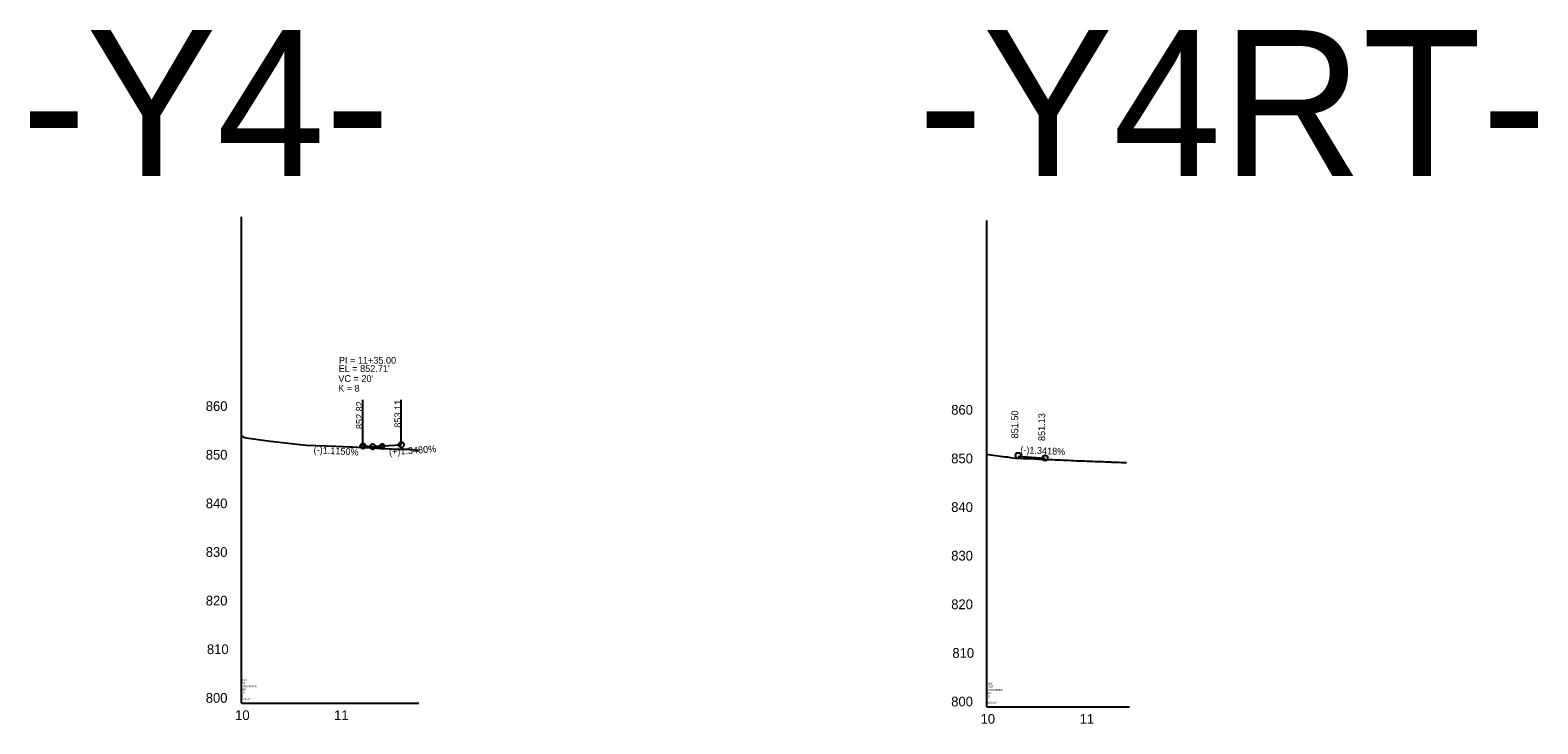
# Model space of a CAD drawing. Extents: x 570622 to 580296, y -55533 to -48575.
# Drawn here: x 577354 to 578904, y -55304 to -54591 of the extents above; entities that cross this region are included whole.
import ezdxf

# ---------------------------------------------------------------- set-up
doc = ezdxf.new("R2010")
doc.units = 0
for name, color, linetype in [('Default', 7, 'Continuous'), ('Exist Profile Cell', 7, 'Continuous'), ('Exist Vertical Profile Ground Line', 7, 'Continuous'), ('Exist Vertical Profile Horizontal Axis Label Major', 7, 'Continuous'), ('Exist Vertical Profile Vertical Axis Label', 7, 'Continuous'), ('Prop Vertical Profile Curve Label', 7, 'Continuous'), ('Prop Vertical Profile Grade', 7, 'Continuous'), ('Prop Vertical Profile Grade Label', 7, 'Continuous'), ('Prop VPI Label', 7, 'Continuous')]:
    doc.layers.add(name, color=color, linetype=linetype)

msp = doc.modelspace()

# ---------------------------------------------------------------- linework, layer by layer
at = {"layer": 'Default'}
for p, q in [((577695.8, -55018.7), (577695.8, -54971.2)), ((577735.2, -55017.2), (577735.2, -54970.9))]:
    msp.add_line(p, q, dxfattribs=at)
at = {"layer": 'Exist Profile Cell'}
for p, q in [((577570.8, -55282.8), (577570.8, -54782.8)), ((578337.3, -55286.6), (578337.3, -54786.6)), ((577570.8, -55282.8), (577753.4, -55282.8)), ((577570.8, -55282.8), (577570.8, -55282.8)), ((578337.3, -55286.6), (578484, -55286.6)), ((578337.3, -55286.6), (578337.3, -55286.6))]:
    msp.add_line(p, q, dxfattribs=at)
at = {"layer": 'Exist Vertical Profile Ground Line'}
for points in [[(577570.8, -55008), (577573, -55009.6), (577575.8, -55010), (577598, -55013.1), (577600.7, -55013.4), (577604, -55013.8), (577630.9, -55016.8), (577631.4, -55016.8), (577637.6, -55017.5), (577667.9, -55018.7), (577681.6, -55019.3), (577685.2, -55019.5), (577690.2, -55019.6), (577709.8, -55020.7), (577712.5, -55020.9), (577714, -55021), (577716.6, -55021.1), (577723.6, -55021.5), (577727.9, -55021.6), (577744.2, -55021.7), (577749.7, -55022.6), (577753.4, -55023.1)], [(578337.3, -55026.9), (578339.2, -55027.2), (578353.7, -55029.2), (578355.9, -55029.5), (578358.6, -55029.8), (578361.4, -55030.2), (578364.1, -55030.6), (578366.8, -55030.9), (578369.5, -55031), (578372.3, -55031.1), (578375, -55031.2), (578377.7, -55031.3), (578380.4, -55031.4), (578383.2, -55031.4), (578385.9, -55031.6), (578386.7, -55031.6), (578387.1, -55031.7), (578387.7, -55031.7), (578388.6, -55031.8), (578391.3, -55031.9), (578394.1, -55032), (578396.8, -55032.1), (578399.5, -55032.3), (578402.3, -55032.4), (578405, -55032.5), (578407.7, -55032.6), (578410.4, -55032.7), (578413.2, -55032.9), (578416.4, -55033), (578418.6, -55033.1), (578421.3, -55033.2), (578424.3, -55033.4), (578426.8, -55033.5), (578429.5, -55033.6), (578432.2, -55033.7), (578435, -55033.8), (578437.7, -55033.9), (578440.4, -55034), (578443.1, -55034.1), (578444.6, -55034.1), (578445.3, -55034.2), (578445.9, -55034.2), (578448.6, -55034.3), (578451.3, -55034.4), (578454.1, -55034.5), (578456.8, -55034.6), (578459.5, -55034.7), (578462.2, -55034.8), (578465, -55034.9), (578465.7, -55035), (578467.7, -55035), (578470.4, -55035.1), (578471.9, -55035.2), (578473.1, -55035.3), (578475.9, -55035.4), (578478.6, -55035.5), (578480.8, -55035.6)]]:
    msp.add_lwpolyline(points, dxfattribs=at)
at = {"layer": 'Prop Vertical Profile Curve Label'}
for centre in [(577695.8, -55018.6), (577715.8, -55018.5)]:
    msp.add_circle(centre, 2.25, dxfattribs=at)
at = {"layer": 'Prop Vertical Profile Grade'}
for p, q in [((577715.8, -55018.5), (577735.2, -55017.2)), ((578369.6, -55029.1), (578397.3, -55030.9))]:
    msp.add_line(p, q, dxfattribs=at)
msp.add_spline([(577695.8, -55018.6), (577696.2, -55018.7), (577696.6, -55018.7), (577697, -55018.7), (577697.4, -55018.7), (577697.8, -55018.7), (577698.2, -55018.8), (577698.6, -55018.8), (577699, -55018.8), (577699.4, -55018.8), (577699.8, -55018.8), (577700.2, -55018.8), (577700.6, -55018.8), (577701, -55018.8), (577701.4, -55018.9), (577701.8, -55018.9), (577702.2, -55018.9), (577702.6, -55018.9), (577703, -55018.9), (577703.4, -55018.9), (577703.8, -55018.9), (577704.2, -55018.9), (577704.6, -55018.9), (577705, -55018.9), (577705.4, -55018.9), (577705.8, -55018.9), (577706.2, -55018.9), (577706.6, -55018.9), (577707, -55018.9), (577707.4, -55018.9), (577707.8, -55018.9), (577708.2, -55018.9), (577708.6, -55018.9), (577709, -55018.8), (577709.4, -55018.8), (577709.8, -55018.8), (577710.2, -55018.8), (577710.6, -55018.8), (577711, -55018.8), (577711.4, -55018.8), (577711.8, -55018.7), (577712.2, -55018.7), (577712.6, -55018.7), (577713, -55018.7), (577713.4, -55018.7), (577713.8, -55018.6), (577714.2, -55018.6), (577714.6, -55018.6), (577715, -55018.6), (577715.4, -55018.6), (577715.8, -55018.5)], degree=3, dxfattribs=at)
at = {"layer": 'Prop VPI Label'}
for p, q in [((577695.8, -55018.6), (577703, -55019)), ((577715.8, -55018.5), (577708.5, -55019))]:
    msp.add_line(p, q, dxfattribs=at)
for centre in [(577695.8, -55018.6), (577695.8, -55018.6), (577705.8, -55019.2), (577735.2, -55017.2), (578369.6, -55028.2), (578397.3, -55030.9)]:
    msp.add_circle(centre, 2.75, dxfattribs=at)

# ---------------------------------------------------------------- texts
at = {"layer": 'Default'}
for s, p in [('-Y4-', (577344.7, -54740.9)), ('-Y4RT-', (578266.5, -54740.9))]:
    msp.add_text(s, height=150, dxfattribs=at).set_placement(p)
at = {"layer": 'Exist Profile Cell'}
for s, p in [('Y4', (577570.8, -55263.3)), ('800', (577570.8, -55269.8)), ('RDY', (577570.8, -55260)), ('1000.000000', (577570.8, -55266.5)), ('Y4RT', (578337.3, -55267.1)), ('RDY', (578337.3, -55263.8)), ('1000.000000', (578337.3, -55270.3)), ('2', (577570.8, -55276.3)), ('10', (577570.8, -55273)), ('NOGAP', (577570.8, -55279.5)), ('800', (578337.3, -55273.6)), ('2', (578337.3, -55280.1)), ('10', (578337.3, -55276.8)), ('NOGAP', (578337.3, -55283.3))]:
    msp.add_text(s, height=2, dxfattribs=at).set_placement(p)
at = {"layer": 'Exist Vertical Profile Horizontal Axis Label Major'}
for s, p in [('10', (577564.4, -55300.3)), ('11', (577666.2, -55300.3)), ('10', (578330.9, -55304.1)), ('11', (578432.7, -55304.1))]:
    msp.add_text(s, height=10, dxfattribs=at).set_placement(p)
at = {"layer": 'Exist Vertical Profile Vertical Axis Label'}
for s, p in [('860', (577534.2, -54982.5)), ('860', (578300.7, -54986.3)), ('850', (577534.2, -55032.5)), ('850', (578300.7, -55036.3)), ('840', (577534.2, -55082.5)), ('840', (578300.7, -55086.3)), ('830', (577534.2, -55132.5)), ('830', (578300.7, -55136.3)), ('820', (577534.2, -55182.5)), ('820', (578300.7, -55186.3)), ('810', (577535.4, -55232.5)), ('810', (578301.9, -55236.3)), ('800', (577534.2, -55282.5)), ('800', (578300.7, -55286.3))]:
    msp.add_text(s, height=10, dxfattribs=at).set_placement(p)
at = {"layer": 'Prop Vertical Profile Curve Label'}
for s, p in [("VC = 20'", (577670.5, -54952.7)), ('K = 8', (577670.3, -54962.7))]:
    msp.add_text(s, height=7, dxfattribs=at).set_placement(p)
at = {"layer": 'Prop Vertical Profile Grade Label'}
for s, rotation, p in [('(-)1.1150%', 356.8091, (577644.9, -55025.8)), ('(+)1.3480%', 3.856, (577722.8, -55028.1)), ('(-)1.3418%', 357.4654, (578371.6, -55025.8))]:
    msp.add_text(s, height=7, rotation=rotation, dxfattribs=at).set_placement(p)
at = {"layer": 'Prop VPI Label'}
for s, p in [('PI = 11+35.00', (577671.1, -54933.9)), ("EL = 852.71'", (577670.8, -54942.4))]:
    msp.add_text(s, height=7, dxfattribs=at).set_placement(p)
for s, p in [('852.82', (577695.8, -55001.1)), ('853.11', (577735.2, -54999.7)), ('851.50', (578369.6, -55010.7)), ('851.13', (578397.3, -55013.4))]:
    msp.add_text(s, height=7, rotation=90, dxfattribs=at).set_placement(p)

doc.saveas('drawing.dxf')
